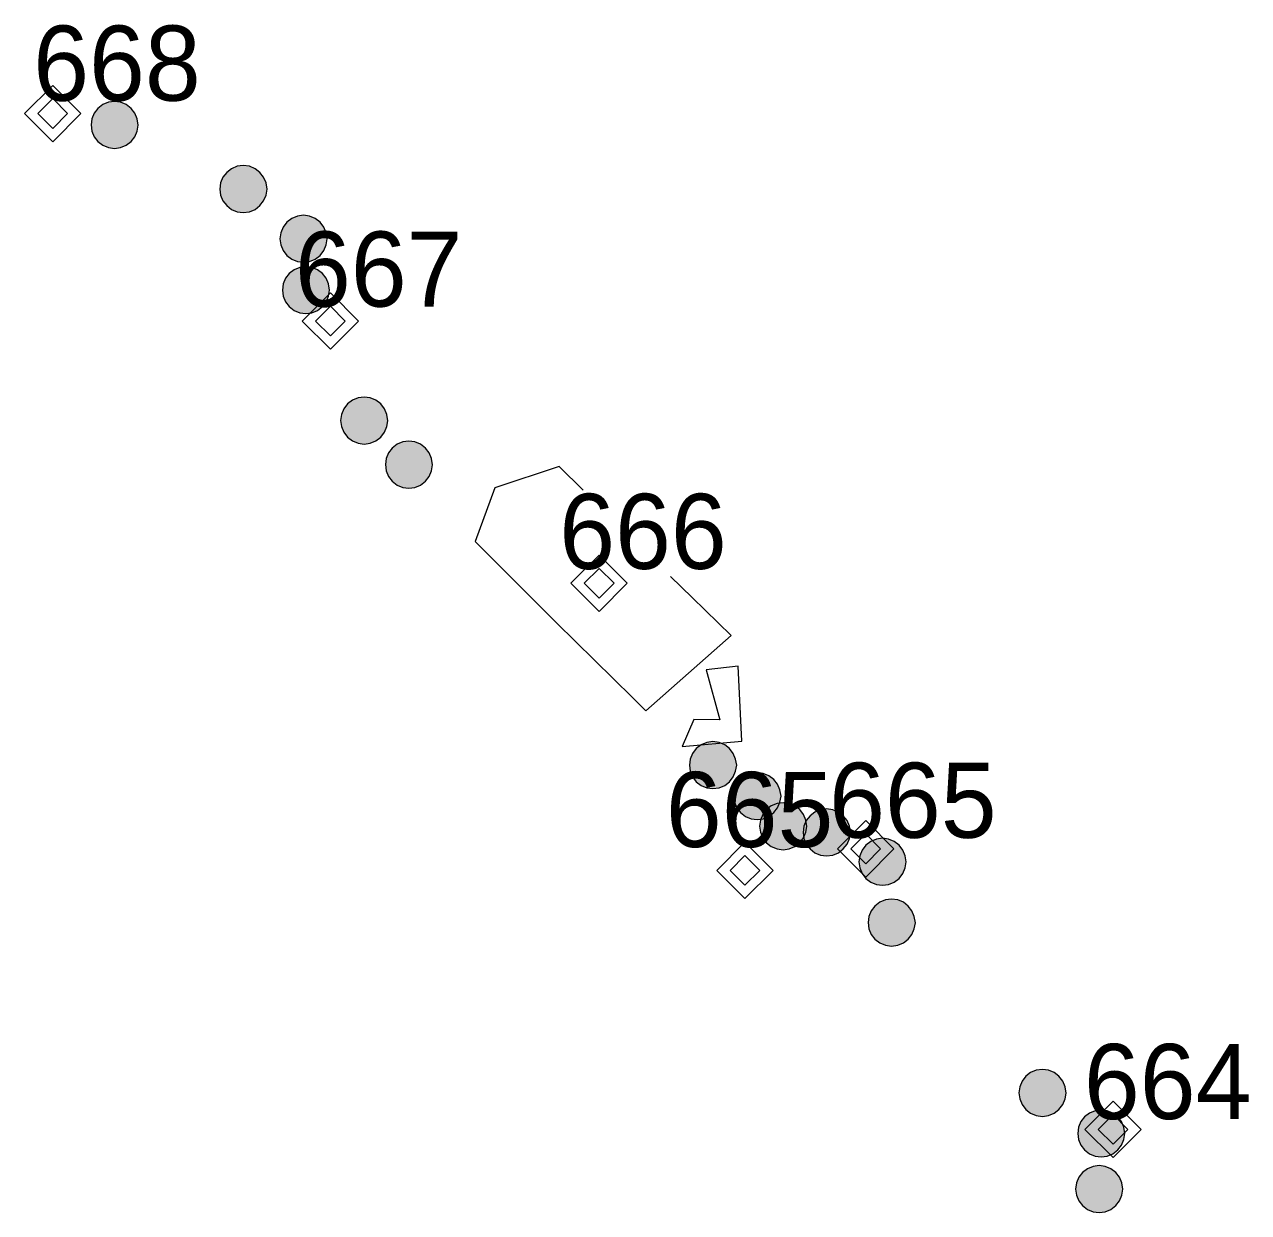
# Model space of a CAD drawing. Extents: x 3461750 to 3585707, y 5917729 to 5985917.
# Drawn here: x 3529325 to 3532584, y 5952861 to 5956026 of the extents above; entities that cross this region are included whole.
import ezdxf

# ---------------------------------------------------------------- set-up
doc = ezdxf.new("R2010")
doc.units = 0
doc.header["$LTSCALE"] = 80
for name, color, linetype, lineweight in [('12', 7, 'Continuous', 13), ('15', 7, 'Continuous', 13), ('2', 7, 'Continuous', 13), ('3', 7, 'Continuous', 13)]:
    doc.layers.add(name, color=color, linetype=linetype, lineweight=lineweight)

msp = doc.modelspace()

# ---------------------------------------------------------------- hatches: boundary and pattern name
at = {"layer": '3'}
for points in [[(3529627.78, 5955757.97), (3529624.85, 5955774.59), (3529618.6, 5955789.69), (3529608.65, 5955802.65), (3529595.69, 5955812.59), (3529580.6, 5955818.84), (3529564.4, 5955820.97), (3529548.21, 5955818.84), (3529533.12, 5955812.59), (3529520.16, 5955802.65), (3529510.21, 5955789.69), (3529503.96, 5955774.59), (3529501.83, 5955758.4), (3529503.96, 5955742.2), (3529510.21, 5955727.11), (3529520.16, 5955714.15), (3529533.12, 5955704.21), (3529548.21, 5955697.96), (3529564.4, 5955695.82), (3529580.6, 5955697.96), (3529595.69, 5955704.21), (3529608.65, 5955714.15), (3529618.6, 5955727.11), (3529624.85, 5955742.2)], [(3529970.75, 5955587.36), (3529967.82, 5955603.99), (3529961.56, 5955619.08), (3529951.62, 5955632.04), (3529938.66, 5955641.98), (3529923.57, 5955648.24), (3529907.37, 5955650.37), (3529891.18, 5955648.24), (3529876.09, 5955641.98), (3529863.13, 5955632.04), (3529853.18, 5955619.08), (3529846.93, 5955603.99), (3529844.8, 5955587.79), (3529846.93, 5955571.6), (3529853.18, 5955556.51), (3529863.13, 5955543.55), (3529876.09, 5955533.6), (3529891.18, 5955527.35), (3529907.37, 5955525.22), (3529923.57, 5955527.35), (3529938.66, 5955533.6), (3529951.62, 5955543.55), (3529961.56, 5955556.51), (3529967.82, 5955571.6)], [(3530130.95, 5955454.75), (3530128.02, 5955471.37), (3530121.77, 5955486.46), (3530111.83, 5955499.42), (3530098.87, 5955509.37), (3530083.77, 5955515.62), (3530067.58, 5955517.75), (3530051.38, 5955515.62), (3530036.29, 5955509.37), (3530023.33, 5955499.42), (3530013.39, 5955486.46), (3530007.14, 5955471.37), (3530005, 5955455.18), (3530007.14, 5955438.98), (3530013.39, 5955423.89), (3530023.33, 5955410.93), (3530036.29, 5955400.98), (3530051.38, 5955394.73), (3530067.58, 5955392.6), (3530083.77, 5955394.73), (3530098.87, 5955400.98), (3530111.83, 5955410.93), (3530121.77, 5955423.89), (3530128.02, 5955438.98)], [(3530137.35, 5955318.22), (3530134.42, 5955334.85), (3530128.17, 5955349.94), (3530118.22, 5955362.9), (3530105.26, 5955372.84), (3530090.17, 5955379.09), (3530073.98, 5955381.23), (3530057.78, 5955379.09), (3530042.69, 5955372.84), (3530029.73, 5955362.9), (3530019.78, 5955349.94), (3530013.53, 5955334.85), (3530011.4, 5955318.65), (3530013.53, 5955302.46), (3530019.78, 5955287.36), (3530029.73, 5955274.4), (3530042.69, 5955264.46), (3530057.78, 5955258.21), (3530073.98, 5955256.08), (3530090.17, 5955258.21), (3530105.26, 5955264.46), (3530118.22, 5955274.4), (3530128.17, 5955287.36), (3530134.42, 5955302.46)], [(3530292.43, 5954970.66), (3530289.5, 5954987.29), (3530283.24, 5955002.38), (3530273.3, 5955015.34), (3530260.34, 5955025.29), (3530245.25, 5955031.54), (3530229.05, 5955033.67), (3530212.86, 5955031.54), (3530197.77, 5955025.29), (3530184.81, 5955015.34), (3530174.86, 5955002.38), (3530168.61, 5954987.29), (3530166.48, 5954971.09), (3530168.61, 5954954.9), (3530174.86, 5954939.81), (3530184.81, 5954926.85), (3530197.77, 5954916.9), (3530212.86, 5954910.65), (3530229.05, 5954908.52), (3530245.25, 5954910.65), (3530260.34, 5954916.9), (3530273.3, 5954926.85), (3530283.24, 5954939.81), (3530289.5, 5954954.9)], [(3530411.61, 5954853.09), (3530408.68, 5954869.71), (3530402.43, 5954884.8), (3530392.49, 5954897.76), (3530379.53, 5954907.71), (3530364.44, 5954913.96), (3530348.24, 5954916.09), (3530332.05, 5954913.96), (3530316.95, 5954907.71), (3530303.99, 5954897.76), (3530294.05, 5954884.8), (3530287.8, 5954869.71), (3530285.67, 5954853.52), (3530287.8, 5954837.32), (3530294.05, 5954822.23), (3530303.99, 5954809.27), (3530316.95, 5954799.32), (3530332.05, 5954793.07), (3530348.24, 5954790.94), (3530364.44, 5954793.07), (3530379.53, 5954799.32), (3530392.49, 5954809.27), (3530402.43, 5954822.23), (3530408.68, 5954837.32)], [(3531221.48, 5954052.7), (3531218.55, 5954069.32), (3531212.3, 5954084.41), (3531202.35, 5954097.37), (3531189.39, 5954107.32), (3531174.3, 5954113.57), (3531158.1, 5954115.7), (3531141.91, 5954113.57), (3531126.82, 5954107.32), (3531113.86, 5954097.37), (3531103.91, 5954084.41), (3531097.66, 5954069.32), (3531095.53, 5954053.12), (3531097.66, 5954036.93), (3531103.91, 5954021.84), (3531113.86, 5954008.88), (3531126.82, 5953998.93), (3531141.91, 5953992.68), (3531158.1, 5953990.55), (3531174.3, 5953992.68), (3531189.39, 5953998.93), (3531202.35, 5954008.88), (3531212.3, 5954021.84), (3531218.55, 5954036.93)], [(3531339.45, 5953970.37), (3531336.52, 5953987), (3531330.27, 5954002.09), (3531320.32, 5954015.05), (3531307.36, 5954024.99), (3531292.27, 5954031.24), (3531276.07, 5954033.38), (3531259.88, 5954031.24), (3531244.79, 5954024.99), (3531231.83, 5954015.05), (3531221.88, 5954002.09), (3531215.63, 5953987), (3531213.5, 5953970.8), (3531215.63, 5953954.61), (3531221.88, 5953939.51), (3531231.83, 5953926.55), (3531244.79, 5953916.61), (3531259.88, 5953910.36), (3531276.07, 5953908.23), (3531292.27, 5953910.36), (3531307.36, 5953916.61), (3531320.32, 5953926.55), (3531330.27, 5953939.51), (3531336.52, 5953954.61)], [(3531408.29, 5953890), (3531405.36, 5953906.63), (3531399.11, 5953921.72), (3531389.17, 5953934.68), (3531376.21, 5953944.62), (3531361.12, 5953950.87), (3531344.92, 5953953.01), (3531328.73, 5953950.87), (3531313.63, 5953944.62), (3531300.67, 5953934.68), (3531290.73, 5953921.72), (3531284.48, 5953906.63), (3531282.35, 5953890.43), (3531284.48, 5953874.23), (3531290.73, 5953859.14), (3531300.67, 5953846.18), (3531313.63, 5953836.24), (3531328.73, 5953829.99), (3531344.92, 5953827.85), (3531361.12, 5953829.99), (3531376.21, 5953836.24), (3531389.17, 5953846.18), (3531399.11, 5953859.14), (3531405.36, 5953874.23)], [(3531524.36, 5953873.59), (3531521.43, 5953890.22), (3531515.18, 5953905.31), (3531505.23, 5953918.27), (3531492.27, 5953928.21), (3531477.18, 5953934.47), (3531460.99, 5953936.6), (3531444.79, 5953934.47), (3531429.7, 5953928.21), (3531416.74, 5953918.27), (3531406.79, 5953905.31), (3531400.54, 5953890.22), (3531398.41, 5953874.02), (3531400.54, 5953857.83), (3531406.79, 5953842.74), (3531416.74, 5953829.78), (3531429.7, 5953819.83), (3531444.79, 5953813.58), (3531460.99, 5953811.45), (3531477.18, 5953813.58), (3531492.27, 5953819.83), (3531505.23, 5953829.78), (3531515.18, 5953842.74), (3531521.43, 5953857.83)], [(3531672.85, 5953795.27), (3531669.92, 5953811.9), (3531663.66, 5953826.99), (3531653.72, 5953839.95), (3531640.76, 5953849.89), (3531625.67, 5953856.15), (3531609.47, 5953858.28), (3531593.28, 5953856.15), (3531578.19, 5953849.89), (3531565.23, 5953839.95), (3531555.28, 5953826.99), (3531549.03, 5953811.9), (3531546.9, 5953795.7), (3531549.03, 5953779.51), (3531555.28, 5953764.42), (3531565.23, 5953751.46), (3531578.19, 5953741.51), (3531593.28, 5953735.26), (3531609.47, 5953733.13), (3531625.67, 5953735.26), (3531640.76, 5953741.51), (3531653.72, 5953751.46), (3531663.66, 5953764.42), (3531669.92, 5953779.51)], [(3531697.31, 5953633.16), (3531694.38, 5953649.79), (3531688.13, 5953664.88), (3531678.18, 5953677.84), (3531665.22, 5953687.79), (3531650.13, 5953694.04), (3531633.94, 5953696.17), (3531617.74, 5953694.04), (3531602.65, 5953687.79), (3531589.69, 5953677.84), (3531579.74, 5953664.88), (3531573.49, 5953649.79), (3531571.36, 5953633.59), (3531573.49, 5953617.4), (3531579.74, 5953602.31), (3531589.69, 5953589.35), (3531602.65, 5953579.4), (3531617.74, 5953573.15), (3531633.94, 5953571.02), (3531650.13, 5953573.15), (3531665.22, 5953579.4), (3531678.18, 5953589.35), (3531688.13, 5953602.31), (3531694.38, 5953617.4)], [(3532098.87, 5953179.55), (3532095.94, 5953196.18), (3532089.69, 5953211.27), (3532079.75, 5953224.23), (3532066.79, 5953234.17), (3532051.69, 5953240.42), (3532035.5, 5953242.56), (3532019.3, 5953240.42), (3532004.21, 5953234.17), (3531991.25, 5953224.23), (3531981.31, 5953211.27), (3531975.06, 5953196.18), (3531972.92, 5953179.98), (3531975.06, 5953163.78), (3531981.31, 5953148.69), (3531991.25, 5953135.73), (3532004.21, 5953125.79), (3532019.3, 5953119.54), (3532035.5, 5953117.4), (3532051.69, 5953119.54), (3532066.79, 5953125.79), (3532079.75, 5953135.73), (3532089.69, 5953148.69), (3532095.94, 5953163.78)], [(3532255.51, 5953071.74), (3532252.58, 5953088.36), (3532246.33, 5953103.46), (3532236.39, 5953116.42), (3532223.43, 5953126.36), (3532208.33, 5953132.61), (3532192.14, 5953134.74), (3532175.94, 5953132.61), (3532160.85, 5953126.36), (3532147.89, 5953116.42), (3532137.95, 5953103.46), (3532131.7, 5953088.36), (3532129.56, 5953072.17), (3532131.7, 5953055.97), (3532137.95, 5953040.88), (3532147.89, 5953027.92), (3532160.85, 5953017.98), (3532175.94, 5953011.73), (3532192.14, 5953009.59), (3532208.33, 5953011.73), (3532223.43, 5953017.98), (3532236.39, 5953027.92), (3532246.33, 5953040.88), (3532252.58, 5953055.97)], [(3532249.9, 5952923.5), (3532246.97, 5952940.12), (3532240.71, 5952955.21), (3532230.77, 5952968.17), (3532217.81, 5952978.12), (3532202.72, 5952984.37), (3532186.52, 5952986.5), (3532170.33, 5952984.37), (3532155.24, 5952978.12), (3532142.28, 5952968.17), (3532132.33, 5952955.21), (3532126.08, 5952940.12), (3532123.95, 5952923.93), (3532126.08, 5952907.73), (3532132.33, 5952892.64), (3532142.28, 5952879.68), (3532155.24, 5952869.73), (3532170.33, 5952863.48), (3532186.52, 5952861.35), (3532202.72, 5952863.48), (3532217.81, 5952869.73), (3532230.77, 5952879.68), (3532240.71, 5952892.64), (3532246.97, 5952907.73)]]:
    msp.add_hatch(color=256, dxfattribs=at).paths.add_polyline_path(points)

# ---------------------------------------------------------------- linework, layer by layer
at = {"layer": '12'}
for points in [[(3531243.39, 5953847.95), (3531168.3, 5953772.86), (3531243.39, 5953697.77), (3531318.48, 5953772.86)], [(3531243.39, 5953812.56), (3531203.7, 5953772.86), (3531243.39, 5953733.17), (3531283.08, 5953772.86)]]:
    msp.add_lwpolyline(points, close=True, dxfattribs=at)
at = {"layer": '15'}
for points in [[(3529399.69, 5955863.87), (3529324.6, 5955788.78), (3529399.69, 5955713.69), (3529474.78, 5955788.78)], [(3529399.69, 5955828.47), (3529360, 5955788.78), (3529399.69, 5955749.09), (3529439.38, 5955788.78)], [(3530139.19, 5955311.14), (3530064.1, 5955236.05), (3530139.19, 5955160.96), (3530214.28, 5955236.05)], [(3530139.19, 5955275.74), (3530099.5, 5955236.05), (3530139.19, 5955196.35), (3530178.89, 5955236.05)], [(3530855.01, 5954612.51), (3530779.92, 5954537.42), (3530855.01, 5954462.32), (3530930.1, 5954537.42)], [(3530855.01, 5954577.11), (3530815.32, 5954537.42), (3530855.01, 5954497.72), (3530894.71, 5954537.42)], [(3531565.12, 5953905.28), (3531490.03, 5953830.19), (3531565.12, 5953755.1), (3531640.21, 5953830.19)], [(3531565.12, 5953869.88), (3531525.43, 5953830.19), (3531565.12, 5953790.5), (3531604.81, 5953830.19)], [(3532223.71, 5953157.92), (3532148.62, 5953082.83), (3532223.71, 5953007.74), (3532298.8, 5953082.83)], [(3532223.71, 5953122.52), (3532184.02, 5953082.83), (3532223.71, 5953043.13), (3532263.41, 5953082.83)]]:
    msp.add_lwpolyline(points, close=True, dxfattribs=at)
at = {"layer": '2'}
for p, q in [((3530812.48, 5954785.9), (3530748.97, 5954848.54)), ((3531206.4, 5954398.54), (3530979.79, 5954197.95))]:
    msp.add_line(p, q, dxfattribs=at)
for points in [[(3530748.97, 5954848.54), (3530576.9, 5954791.41), (3530524.46, 5954648.63)], [(3530979.79, 5954197.95), (3530943.75, 5954233.5), (3530741.8, 5954432.52), (3530564.36, 5954609.38), (3530524.46, 5954648.63)], [(3531206.4, 5954398.54), (3531102.44, 5954499.51), (3531045.37, 5954555.9)]]:
    msp.add_lwpolyline(points, dxfattribs=at)
msp.add_lwpolyline([(3531076.37, 5954102.44), (3531235.11, 5954117.29), (3531225.15, 5954317.09), (3531140.33, 5954306.84), (3531176.32, 5954173.34), (3531107.18, 5954175)], close=True, dxfattribs=at)
at = {"layer": '3'}
for points in [[(3529627.78, 5955757.97), (3529624.85, 5955774.59), (3529618.6, 5955789.69), (3529608.65, 5955802.65), (3529595.69, 5955812.59), (3529580.6, 5955818.84), (3529564.4, 5955820.97), (3529548.21, 5955818.84), (3529533.12, 5955812.59), (3529520.16, 5955802.65), (3529510.21, 5955789.69), (3529503.96, 5955774.59), (3529501.83, 5955758.4), (3529503.96, 5955742.2), (3529510.21, 5955727.11), (3529520.16, 5955714.15), (3529533.12, 5955704.21), (3529548.21, 5955697.96), (3529564.4, 5955695.82), (3529580.6, 5955697.96), (3529595.69, 5955704.21), (3529608.65, 5955714.15), (3529618.6, 5955727.11), (3529624.85, 5955742.2)], [(3529970.75, 5955587.36), (3529967.82, 5955603.99), (3529961.56, 5955619.08), (3529951.62, 5955632.04), (3529938.66, 5955641.98), (3529923.57, 5955648.24), (3529907.37, 5955650.37), (3529891.18, 5955648.24), (3529876.09, 5955641.98), (3529863.13, 5955632.04), (3529853.18, 5955619.08), (3529846.93, 5955603.99), (3529844.8, 5955587.79), (3529846.93, 5955571.6), (3529853.18, 5955556.51), (3529863.13, 5955543.55), (3529876.09, 5955533.6), (3529891.18, 5955527.35), (3529907.37, 5955525.22), (3529923.57, 5955527.35), (3529938.66, 5955533.6), (3529951.62, 5955543.55), (3529961.56, 5955556.51), (3529967.82, 5955571.6)], [(3530130.95, 5955454.75), (3530128.02, 5955471.37), (3530121.77, 5955486.46), (3530111.83, 5955499.42), (3530098.87, 5955509.37), (3530083.77, 5955515.62), (3530067.58, 5955517.75), (3530051.38, 5955515.62), (3530036.29, 5955509.37), (3530023.33, 5955499.42), (3530013.39, 5955486.46), (3530007.14, 5955471.37), (3530005, 5955455.18), (3530007.14, 5955438.98), (3530013.39, 5955423.89), (3530023.33, 5955410.93), (3530036.29, 5955400.98), (3530051.38, 5955394.73), (3530067.58, 5955392.6), (3530083.77, 5955394.73), (3530098.87, 5955400.98), (3530111.83, 5955410.93), (3530121.77, 5955423.89), (3530128.02, 5955438.98)], [(3530137.35, 5955318.22), (3530134.42, 5955334.85), (3530128.17, 5955349.94), (3530118.22, 5955362.9), (3530105.26, 5955372.84), (3530090.17, 5955379.09), (3530073.98, 5955381.23), (3530057.78, 5955379.09), (3530042.69, 5955372.84), (3530029.73, 5955362.9), (3530019.78, 5955349.94), (3530013.53, 5955334.85), (3530011.4, 5955318.65), (3530013.53, 5955302.46), (3530019.78, 5955287.36), (3530029.73, 5955274.4), (3530042.69, 5955264.46), (3530057.78, 5955258.21), (3530073.98, 5955256.08), (3530090.17, 5955258.21), (3530105.26, 5955264.46), (3530118.22, 5955274.4), (3530128.17, 5955287.36), (3530134.42, 5955302.46)], [(3530292.43, 5954970.66), (3530289.5, 5954987.29), (3530283.24, 5955002.38), (3530273.3, 5955015.34), (3530260.34, 5955025.29), (3530245.25, 5955031.54), (3530229.05, 5955033.67), (3530212.86, 5955031.54), (3530197.77, 5955025.29), (3530184.81, 5955015.34), (3530174.86, 5955002.38), (3530168.61, 5954987.29), (3530166.48, 5954971.09), (3530168.61, 5954954.9), (3530174.86, 5954939.81), (3530184.81, 5954926.85), (3530197.77, 5954916.9), (3530212.86, 5954910.65), (3530229.05, 5954908.52), (3530245.25, 5954910.65), (3530260.34, 5954916.9), (3530273.3, 5954926.85), (3530283.24, 5954939.81), (3530289.5, 5954954.9)], [(3530411.61, 5954853.09), (3530408.68, 5954869.71), (3530402.43, 5954884.8), (3530392.49, 5954897.76), (3530379.53, 5954907.71), (3530364.44, 5954913.96), (3530348.24, 5954916.09), (3530332.05, 5954913.96), (3530316.95, 5954907.71), (3530303.99, 5954897.76), (3530294.05, 5954884.8), (3530287.8, 5954869.71), (3530285.67, 5954853.52), (3530287.8, 5954837.32), (3530294.05, 5954822.23), (3530303.99, 5954809.27), (3530316.95, 5954799.32), (3530332.05, 5954793.07), (3530348.24, 5954790.94), (3530364.44, 5954793.07), (3530379.53, 5954799.32), (3530392.49, 5954809.27), (3530402.43, 5954822.23), (3530408.68, 5954837.32)], [(3531221.48, 5954052.7), (3531218.55, 5954069.32), (3531212.3, 5954084.41), (3531202.35, 5954097.37), (3531189.39, 5954107.32), (3531174.3, 5954113.57), (3531158.1, 5954115.7), (3531141.91, 5954113.57), (3531126.82, 5954107.32), (3531113.86, 5954097.37), (3531103.91, 5954084.41), (3531097.66, 5954069.32), (3531095.53, 5954053.12), (3531097.66, 5954036.93), (3531103.91, 5954021.84), (3531113.86, 5954008.88), (3531126.82, 5953998.93), (3531141.91, 5953992.68), (3531158.1, 5953990.55), (3531174.3, 5953992.68), (3531189.39, 5953998.93), (3531202.35, 5954008.88), (3531212.3, 5954021.84), (3531218.55, 5954036.93)], [(3531339.45, 5953970.37), (3531336.52, 5953987), (3531330.27, 5954002.09), (3531320.32, 5954015.05), (3531307.36, 5954024.99), (3531292.27, 5954031.24), (3531276.07, 5954033.38), (3531259.88, 5954031.24), (3531244.79, 5954024.99), (3531231.83, 5954015.05), (3531221.88, 5954002.09), (3531215.63, 5953987), (3531213.5, 5953970.8), (3531215.63, 5953954.61), (3531221.88, 5953939.51), (3531231.83, 5953926.55), (3531244.79, 5953916.61), (3531259.88, 5953910.36), (3531276.07, 5953908.23), (3531292.27, 5953910.36), (3531307.36, 5953916.61), (3531320.32, 5953926.55), (3531330.27, 5953939.51), (3531336.52, 5953954.61)], [(3531408.29, 5953890), (3531405.36, 5953906.63), (3531399.11, 5953921.72), (3531389.17, 5953934.68), (3531376.21, 5953944.62), (3531361.12, 5953950.87), (3531344.92, 5953953.01), (3531328.73, 5953950.87), (3531313.63, 5953944.62), (3531300.67, 5953934.68), (3531290.73, 5953921.72), (3531284.48, 5953906.63), (3531282.35, 5953890.43), (3531284.48, 5953874.23), (3531290.73, 5953859.14), (3531300.67, 5953846.18), (3531313.63, 5953836.24), (3531328.73, 5953829.99), (3531344.92, 5953827.85), (3531361.12, 5953829.99), (3531376.21, 5953836.24), (3531389.17, 5953846.18), (3531399.11, 5953859.14), (3531405.36, 5953874.23)], [(3531524.36, 5953873.59), (3531521.43, 5953890.22), (3531515.18, 5953905.31), (3531505.23, 5953918.27), (3531492.27, 5953928.21), (3531477.18, 5953934.47), (3531460.99, 5953936.6), (3531444.79, 5953934.47), (3531429.7, 5953928.21), (3531416.74, 5953918.27), (3531406.79, 5953905.31), (3531400.54, 5953890.22), (3531398.41, 5953874.02), (3531400.54, 5953857.83), (3531406.79, 5953842.74), (3531416.74, 5953829.78), (3531429.7, 5953819.83), (3531444.79, 5953813.58), (3531460.99, 5953811.45), (3531477.18, 5953813.58), (3531492.27, 5953819.83), (3531505.23, 5953829.78), (3531515.18, 5953842.74), (3531521.43, 5953857.83)], [(3531672.85, 5953795.27), (3531669.92, 5953811.9), (3531663.66, 5953826.99), (3531653.72, 5953839.95), (3531640.76, 5953849.89), (3531625.67, 5953856.15), (3531609.47, 5953858.28), (3531593.28, 5953856.15), (3531578.19, 5953849.89), (3531565.23, 5953839.95), (3531555.28, 5953826.99), (3531549.03, 5953811.9), (3531546.9, 5953795.7), (3531549.03, 5953779.51), (3531555.28, 5953764.42), (3531565.23, 5953751.46), (3531578.19, 5953741.51), (3531593.28, 5953735.26), (3531609.47, 5953733.13), (3531625.67, 5953735.26), (3531640.76, 5953741.51), (3531653.72, 5953751.46), (3531663.66, 5953764.42), (3531669.92, 5953779.51)], [(3531697.31, 5953633.16), (3531694.38, 5953649.79), (3531688.13, 5953664.88), (3531678.18, 5953677.84), (3531665.22, 5953687.79), (3531650.13, 5953694.04), (3531633.94, 5953696.17), (3531617.74, 5953694.04), (3531602.65, 5953687.79), (3531589.69, 5953677.84), (3531579.74, 5953664.88), (3531573.49, 5953649.79), (3531571.36, 5953633.59), (3531573.49, 5953617.4), (3531579.74, 5953602.31), (3531589.69, 5953589.35), (3531602.65, 5953579.4), (3531617.74, 5953573.15), (3531633.94, 5953571.02), (3531650.13, 5953573.15), (3531665.22, 5953579.4), (3531678.18, 5953589.35), (3531688.13, 5953602.31), (3531694.38, 5953617.4)], [(3532098.87, 5953179.55), (3532095.94, 5953196.18), (3532089.69, 5953211.27), (3532079.75, 5953224.23), (3532066.79, 5953234.17), (3532051.69, 5953240.42), (3532035.5, 5953242.56), (3532019.3, 5953240.42), (3532004.21, 5953234.17), (3531991.25, 5953224.23), (3531981.31, 5953211.27), (3531975.06, 5953196.18), (3531972.92, 5953179.98), (3531975.06, 5953163.78), (3531981.31, 5953148.69), (3531991.25, 5953135.73), (3532004.21, 5953125.79), (3532019.3, 5953119.54), (3532035.5, 5953117.4), (3532051.69, 5953119.54), (3532066.79, 5953125.79), (3532079.75, 5953135.73), (3532089.69, 5953148.69), (3532095.94, 5953163.78)], [(3532255.51, 5953071.74), (3532252.58, 5953088.36), (3532246.33, 5953103.46), (3532236.39, 5953116.42), (3532223.43, 5953126.36), (3532208.33, 5953132.61), (3532192.14, 5953134.74), (3532175.94, 5953132.61), (3532160.85, 5953126.36), (3532147.89, 5953116.42), (3532137.95, 5953103.46), (3532131.7, 5953088.36), (3532129.56, 5953072.17), (3532131.7, 5953055.97), (3532137.95, 5953040.88), (3532147.89, 5953027.92), (3532160.85, 5953017.98), (3532175.94, 5953011.73), (3532192.14, 5953009.59), (3532208.33, 5953011.73), (3532223.43, 5953017.98), (3532236.39, 5953027.92), (3532246.33, 5953040.88), (3532252.58, 5953055.97)], [(3532249.9, 5952923.5), (3532246.97, 5952940.12), (3532240.71, 5952955.21), (3532230.77, 5952968.17), (3532217.81, 5952978.12), (3532202.72, 5952984.37), (3532186.52, 5952986.5), (3532170.33, 5952984.37), (3532155.24, 5952978.12), (3532142.28, 5952968.17), (3532132.33, 5952955.21), (3532126.08, 5952940.12), (3532123.95, 5952923.93), (3532126.08, 5952907.73), (3532132.33, 5952892.64), (3532142.28, 5952879.68), (3532155.24, 5952869.73), (3532170.33, 5952863.48), (3532186.52, 5952861.35), (3532202.72, 5952863.48), (3532217.81, 5952869.73), (3532230.77, 5952879.68), (3532240.71, 5952892.64), (3532246.97, 5952907.73)]]:
    msp.add_lwpolyline(points, close=True, dxfattribs=at)

# ---------------------------------------------------------------- texts
at = {"layer": '12'}
msp.add_text('665', height=200, dxfattribs=at).set_placement((3531032.7, 5953835))
at = {"layer": '15'}
for s, p in [('668', (3529347.8, 5955823.1)), ('667', (3530045, 5955274.6)), ('666', (3530748.7, 5954575.9)), ('665', (3531467.5, 5953859.6)), ('664', (3532146.1, 5953110.4))]:
    msp.add_text(s, height=200, dxfattribs=at).set_placement(p)

doc.saveas('drawing.dxf')
